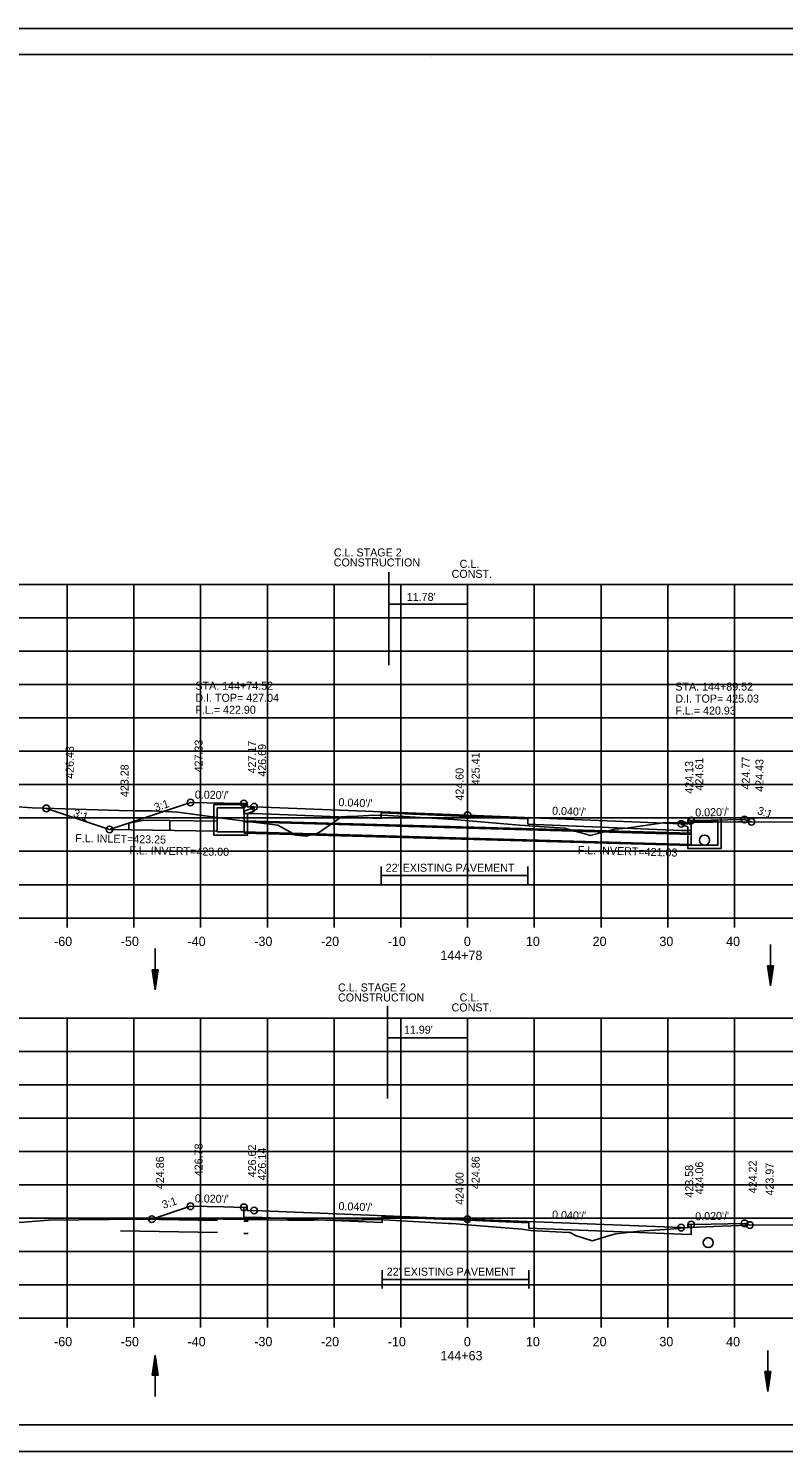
# Model space of a CAD drawing. Extents: x 1538688 to 1540766, y 656250 to 671912.
# Drawn here: x 1538792.4 to 1538905.5, y 663378.1 to 663591.4 of the extents above; entities that cross this region are included whole.
import ezdxf

# ---------------------------------------------------------------- set-up
doc = ezdxf.new("R2010")
doc.units = 0
for name, color, linetype in [('15', 7, 'Continuous'), ('18', 7, 'Continuous'), ('20', 7, 'Continuous'), ('22', 7, 'Continuous'), ('26', 7, 'Continuous'), ('39', 7, 'Continuous'), ('40', 7, 'Continuous'), ('41', 7, 'Continuous'), ('42', 7, 'Continuous'), ('7', 7, 'Continuous'), ('Borings', 7, 'Continuous'), ('Default', 7, 'Continuous'), ('Horizontal Alignment', 7, 'Continuous'), ('RipRap', 7, 'Continuous'), ('Wall Heights', 7, 'Continuous')]:
    doc.layers.add(name, color=color, linetype=linetype)

msp = doc.modelspace()

# ---------------------------------------------------------------- linework, layer by layer
at = {"layer": '15'}
for p, q in [((1538810.92, 663450.29), (1538811.37, 663447.29)), ((1538810.92, 663450.29), (1538811.82, 663450.29)), ((1538811, 663450.29), (1538811.37, 663447.79)), ((1538811.07, 663450.29), (1538811.37, 663448.3)), ((1538811.15, 663450.29), (1538811.37, 663448.8)), ((1538811.23, 663450.29), (1538811.37, 663449.31)), ((1538811.3, 663450.29), (1538811.37, 663449.81)), ((1538811.82, 663450.29), (1538811.37, 663447.29)), ((1538811.52, 663450.29), (1538811.37, 663449.31)), ((1538811.67, 663450.29), (1538811.37, 663448.3)), ((1538811.75, 663450.29), (1538811.37, 663447.79)), ((1538811.59, 663450.29), (1538811.37, 663448.8)), ((1538811.44, 663450.29), (1538811.37, 663449.81)), ((1538903.12, 663450.86), (1538903.57, 663447.86)), ((1538903.12, 663450.86), (1538904.02, 663450.86)), ((1538903.2, 663450.86), (1538903.57, 663448.36)), ((1538903.27, 663450.86), (1538903.57, 663448.88)), ((1538903.35, 663450.86), (1538903.57, 663449.38)), ((1538903.43, 663450.86), (1538903.57, 663449.89)), ((1538903.5, 663450.86), (1538903.57, 663450.39)), ((1538904.02, 663450.86), (1538903.57, 663447.86)), ((1538903.72, 663450.86), (1538903.57, 663449.89)), ((1538903.87, 663450.86), (1538903.57, 663448.88)), ((1538903.95, 663450.86), (1538903.57, 663448.36)), ((1538903.79, 663450.86), (1538903.57, 663449.38)), ((1538903.64, 663450.86), (1538903.57, 663450.39)), ((1538810.92, 663389.48), (1538811.37, 663392.48)), ((1538811.82, 663389.48), (1538811.37, 663392.48)), ((1538811, 663389.48), (1538811.37, 663391.98)), ((1538811.07, 663389.48), (1538811.37, 663391.46)), ((1538811.15, 663389.48), (1538811.37, 663390.96)), ((1538811.23, 663389.48), (1538811.37, 663390.45)), ((1538811.75, 663389.48), (1538811.37, 663391.98)), ((1538811.67, 663389.48), (1538811.37, 663391.46)), ((1538811.59, 663389.48), (1538811.37, 663390.96)), ((1538811.52, 663389.48), (1538811.37, 663390.45)), ((1538810.92, 663389.48), (1538811.82, 663389.48)), ((1538811.3, 663389.48), (1538811.37, 663389.95)), ((1538811.44, 663389.48), (1538811.37, 663389.95)), ((1538902.72, 663390.03), (1538903.17, 663387.03)), ((1538902.72, 663390.03), (1538903.62, 663390.03)), ((1538902.8, 663390.03), (1538903.17, 663387.54)), ((1538902.87, 663390.03), (1538903.17, 663388.05)), ((1538902.95, 663390.03), (1538903.17, 663388.55)), ((1538903.02, 663390.03), (1538903.17, 663389.06)), ((1538903.1, 663390.03), (1538903.17, 663389.56)), ((1538903.62, 663390.03), (1538903.17, 663387.03)), ((1538903.32, 663390.03), (1538903.17, 663389.06)), ((1538903.47, 663390.03), (1538903.17, 663388.05)), ((1538903.55, 663390.03), (1538903.17, 663387.54)), ((1538903.39, 663390.03), (1538903.17, 663388.55)), ((1538903.24, 663390.03), (1538903.17, 663389.56))]:
    msp.add_line(p, q, dxfattribs=at)
at = {"layer": '18'}
for points in [[(1538790.08, 663474.76), (1538792.95, 663474.53), (1538805.98, 663474.15), (1538808.36, 663474.1), (1538809.55, 663474.1), (1538810.94, 663474.11), (1538814.75, 663473.89), (1538823.98, 663472.66), (1538829.73, 663471.93), (1538831.53, 663470.96), (1538832.42, 663470.46), (1538834.02, 663470.3), (1538835.2, 663470.67), (1538835.61, 663470.68), (1538835.97, 663470.88), (1538839.3, 663473.22), (1538840.06, 663473.24), (1538840.87, 663473.27), (1538843.36, 663473.39), (1538844.95, 663473.45), (1538846.21, 663473.38), (1538856.06, 663472.81), (1538856.08, 663472.81), (1538865.94, 663471.97), (1538866.72, 663471.91), (1538866.84, 663471.9), (1538867.41, 663471.86), (1538872.69, 663471.52), (1538875.75, 663470.64), (1538876.57, 663470.38), (1538877.16, 663470.57), (1538880.25, 663471.34), (1538881.98, 663471.51), (1538887.47, 663472.29), (1538898.67, 663472.45), (1538898.91, 663472.46), (1538899.33, 663472.46), (1538922.45, 663472.39)], [(1538790.99, 663412.39), (1538795.38, 663412.73), (1538804.48, 663412.85), (1538813.49, 663412.91), (1538817.58, 663412.95), (1538821.55, 663412.89), (1538831.35, 663412.76), (1538835.22, 663412.74), (1538842.32, 663412.78), (1538842.73, 663412.78), (1538844.79, 663412.85), (1538855.29, 663412.26), (1538855.73, 663412.24), (1538855.85, 663412.23), (1538858.22, 663412.03), (1538866.31, 663411.4), (1538867.64, 663411.21), (1538869.46, 663411.11), (1538873.33, 663410.91), (1538873.55, 663410.91), (1538874.33, 663410.43), (1538876.83, 663409.63), (1538880, 663410.61), (1538880.39, 663410.71), (1538883.94, 663411.07), (1538888.53, 663411.4), (1538891.29, 663411.64), (1538900.19, 663412), (1538918.65, 663412.09)]]:
    msp.add_lwpolyline(points, dxfattribs=at)
at = {"layer": '20'}
for points in [[(1538795.06, 663474.47), (1538804.53, 663471.31), (1538816.67, 663475.36), (1538821.67, 663475.26), (1538824.67, 663475.2), (1538825.17, 663475.2), (1538825.18, 663474.7), (1538826.18, 663474.72), (1538858.18, 663473.44), (1538890.18, 663472.16), (1538891.18, 663472.14), (1538891.19, 663472.64), (1538891.69, 663472.64), (1538894.69, 663472.7), (1538899.69, 663472.8), (1538900.72, 663472.46)], [(1538810.88, 663412.89), (1538816.67, 663414.82), (1538821.67, 663414.72), (1538824.67, 663414.66), (1538825.17, 663414.66), (1538825.18, 663414.16), (1538826.18, 663414.18), (1538858.18, 663412.9), (1538890.18, 663411.62), (1538891.18, 663411.6), (1538891.19, 663412.1), (1538891.69, 663412.1), (1538894.69, 663412.16), (1538899.69, 663412.26), (1538900.45, 663412.01)]]:
    msp.add_lwpolyline(points, dxfattribs=at)
at = {"layer": '22'}
for p, q in [((1538718.18, 663508.03), (1538998.18, 663508.03)), ((1538798.18, 663458.03), (1538798.18, 663508.03)), ((1538808.18, 663458.03), (1538808.18, 663508.03)), ((1538818.18, 663458.03), (1538818.18, 663508.03)), ((1538828.18, 663458.03), (1538828.18, 663508.03)), ((1538838.18, 663458.03), (1538838.18, 663508.03)), ((1538848.18, 663458.03), (1538848.18, 663508.03)), ((1538858.18, 663458.03), (1538858.18, 663508.03)), ((1538868.18, 663458.03), (1538868.18, 663508.03)), ((1538878.18, 663458.03), (1538878.18, 663508.03)), ((1538888.18, 663458.03), (1538888.18, 663508.03)), ((1538898.18, 663458.03), (1538898.18, 663508.03)), ((1538718.18, 663503.03), (1538998.18, 663503.03)), ((1538718.18, 663498.03), (1538998.18, 663498.03)), ((1538718.18, 663493.03), (1538998.18, 663493.03)), ((1538718.18, 663488.03), (1538998.18, 663488.03)), ((1538718.18, 663483.03), (1538998.18, 663483.03)), ((1538718.18, 663478.03), (1538998.18, 663478.03)), ((1538718.18, 663473.03), (1538998.18, 663473.03)), ((1538718.18, 663468.03), (1538998.18, 663468.03)), ((1538718.18, 663463.03), (1538998.18, 663463.03)), ((1538718.18, 663458.03), (1538998.18, 663458.03)), ((1538718.18, 663443.03), (1538998.18, 663443.03)), ((1538798.18, 663398.03), (1538798.18, 663443.03)), ((1538808.18, 663398.03), (1538808.18, 663443.03)), ((1538818.18, 663398.03), (1538818.18, 663443.03)), ((1538828.18, 663398.03), (1538828.18, 663443.03)), ((1538838.18, 663398.03), (1538838.18, 663443.03)), ((1538848.18, 663398.03), (1538848.18, 663443.03)), ((1538858.18, 663398.03), (1538858.18, 663443.03)), ((1538868.18, 663398.03), (1538868.18, 663443.03)), ((1538878.18, 663398.03), (1538878.18, 663443.03)), ((1538888.18, 663398.03), (1538888.18, 663443.03)), ((1538898.18, 663398.03), (1538898.18, 663443.03)), ((1538718.18, 663438.03), (1538998.18, 663438.03)), ((1538718.18, 663433.03), (1538998.18, 663433.03)), ((1538718.18, 663428.03), (1538998.18, 663428.03)), ((1538718.18, 663423.03), (1538998.18, 663423.03)), ((1538718.18, 663418.03), (1538998.18, 663418.03)), ((1538718.18, 663413.03), (1538998.18, 663413.03)), ((1538718.18, 663408.03), (1538998.18, 663408.03)), ((1538718.18, 663403.03), (1538998.18, 663403.03)), ((1538718.18, 663398.03), (1538998.18, 663398.03))]:
    msp.add_line(p, q, dxfattribs=at)
at = {"layer": '26'}
for p, q in [((1538687.78, 663591.39), (1539021.11, 663591.39)), ((1538824.64, 663472.6), (1538891.73, 663470.73)), ((1538824.64, 663470.76), (1538891.73, 663468.9)), ((1538806.19, 663412.95), (1538820.69, 663412.7)), ((1538824.64, 663412.6), (1538825.31, 663412.58)), ((1538806.19, 663411.12), (1538820.69, 663410.87)), ((1538824.64, 663410.76), (1538825.31, 663410.75)), ((1538687.78, 663378.06), (1539021.11, 663378.06))]:
    msp.add_line(p, q, dxfattribs=at)
msp.add_lwpolyline([(1538687.77, 663591.39), (1539021.11, 663591.39), (1539021.11, 663378.05), (1538687.77, 663378.05)], close=True, dxfattribs=at)
for centre in [(1538816.67, 663475.36), (1538824.67, 663475.2), (1538795.06, 663474.47), (1538826.18, 663474.72), (1538858.18, 663473.44), (1538804.53, 663471.31), (1538890.18, 663472.16), (1538891.69, 663472.64), (1538899.69, 663472.8), (1538900.71, 663472.46), (1538816.67, 663414.82), (1538824.67, 663414.66), (1538826.18, 663414.18), (1538810.88, 663412.89), (1538858.18, 663412.9), (1538890.18, 663411.62), (1538891.69, 663412.1), (1538899.69, 663412.26), (1538900.45, 663412.01)]:
    msp.add_circle(centre, 0.5, dxfattribs=at)
at = {"layer": '39'}
for p, q in [((1538820.18, 663475.07), (1538824.93, 663475.07)), ((1538820.18, 663473.57), (1538820.18, 663475.07)), ((1538820.68, 663473.57), (1538820.68, 663474.57)), ((1538820.68, 663474.57), (1538824.68, 663474.57)), ((1538825.01, 663474.91), (1538824.68, 663474.57)), ((1538826.18, 663474.59), (1538824.68, 663474.07)), ((1538824.68, 663473.57), (1538824.68, 663474.07)), ((1538825.01, 663474.91), (1538824.93, 663475.07)), ((1538826.18, 663474.06), (1538825.18, 663473.72)), ((1538825.18, 663473.57), (1538825.18, 663473.72)), ((1538813.54, 663472.66), (1538820.69, 663472.53)), ((1538824.64, 663472.43), (1538891.73, 663470.57)), ((1538890.18, 663472.59), (1538891.68, 663472.07)), ((1538890.18, 663472.06), (1538891.18, 663471.71)), ((1538891.18, 663471.57), (1538891.18, 663471.71)), ((1538891.34, 663472.9), (1538891.43, 663473.07)), ((1538891.34, 663472.9), (1538891.68, 663472.57)), ((1538896.18, 663473.07), (1538891.43, 663473.07)), ((1538895.68, 663472.57), (1538891.68, 663472.57)), ((1538891.68, 663471.57), (1538891.68, 663472.07)), ((1538895.68, 663471.57), (1538895.68, 663472.57)), ((1538896.18, 663471.57), (1538896.18, 663473.07)), ((1538804.53, 663471.31), (1538820.69, 663471.03)), ((1538824.64, 663470.93), (1538891.73, 663469.07)), ((1538811.37, 663453.48), (1538811.37, 663447.29)), ((1538903.57, 663454.05), (1538903.57, 663447.86)), ((1538811.37, 663386.29), (1538811.37, 663392.48)), ((1538903.17, 663393.22), (1538903.17, 663387.03))]:
    msp.add_line(p, q, dxfattribs=at)
for points in [[(1538825.18, 663473.57), (1538825.18, 663470.43), (1538822.68, 663470.43), (1538820.18, 663470.43), (1538820.18, 663473.57)], [(1538824.68, 663473.57), (1538824.68, 663470.93), (1538822.68, 663470.93), (1538820.68, 663470.93), (1538820.68, 663473.57)], [(1538826.18, 663474.06), (1538826.18, 663474.59)], [(1538807.44, 663471.26), (1538807.41, 663472.26), (1538809.71, 663472.72), (1538813.54, 663472.66), (1538813.58, 663471.16)], [(1538890.18, 663472.06), (1538890.18, 663472.59)], [(1538896.18, 663471.57), (1538896.18, 663468.47), (1538893.68, 663468.47), (1538891.18, 663468.47), (1538891.18, 663471.57)], [(1538895.68, 663471.57), (1538895.68, 663468.97), (1538893.68, 663468.97), (1538891.68, 663468.97), (1538891.68, 663471.57)]]:
    msp.add_lwpolyline(points, dxfattribs=at)
for centre in [(1538893.68, 663469.72), (1538894.24, 663409.37)]:
    msp.add_circle(centre, 0.75, dxfattribs=at)
at = {"layer": '7'}
for p, q in [((1538845.21, 663465.78), (1538845.21, 663463.04)), ((1538867.21, 663465.78), (1538867.21, 663463.04)), ((1538867.21, 663464.41), (1538845.21, 663464.41)), ((1538845.36, 663405.24), (1538845.36, 663402.49)), ((1538867.36, 663403.86), (1538845.36, 663403.86)), ((1538867.36, 663405.24), (1538867.36, 663402.49))]:
    msp.add_line(p, q, dxfattribs=at)
at = {"layer": 'Borings'}
for p, q in [((1538718.18, 663458.03), (1538998.18, 663458.03)), ((1538798.18, 663456.63), (1538798.18, 663458.03)), ((1538808.18, 663456.63), (1538808.18, 663458.03)), ((1538818.18, 663456.63), (1538818.18, 663458.03)), ((1538828.18, 663456.63), (1538828.18, 663458.03)), ((1538838.18, 663456.63), (1538838.18, 663458.03)), ((1538848.18, 663456.63), (1538848.18, 663458.03)), ((1538858.18, 663456.63), (1538858.18, 663458.03)), ((1538868.18, 663456.63), (1538868.18, 663458.03)), ((1538878.18, 663456.63), (1538878.18, 663458.03)), ((1538888.18, 663456.63), (1538888.18, 663458.03)), ((1538898.18, 663456.63), (1538898.18, 663458.03)), ((1538718.18, 663398.03), (1538998.18, 663398.03)), ((1538798.18, 663396.63), (1538798.18, 663398.03)), ((1538808.18, 663396.63), (1538808.18, 663398.03)), ((1538818.18, 663396.63), (1538818.18, 663398.03)), ((1538828.18, 663396.63), (1538828.18, 663398.03)), ((1538838.18, 663396.63), (1538838.18, 663398.03)), ((1538848.18, 663396.63), (1538848.18, 663398.03)), ((1538858.18, 663396.63), (1538858.18, 663398.03)), ((1538868.18, 663396.63), (1538868.18, 663398.03)), ((1538878.18, 663396.63), (1538878.18, 663398.03)), ((1538888.18, 663396.63), (1538888.18, 663398.03)), ((1538898.18, 663396.63), (1538898.18, 663398.03))]:
    msp.add_line(p, q, dxfattribs=at)
at = {"layer": 'Default'}
for p, q in [((1538846.4, 663509.87), (1538846.4, 663495.96)), ((1538858.18, 663507.58), (1538858.18, 663502.58)), ((1538858.18, 663505.08), (1538846.4, 663505.08)), ((1538846.19, 663444.87), (1538846.19, 663430.96)), ((1538858.18, 663442.58), (1538858.18, 663437.58)), ((1538858.18, 663440.08), (1538846.19, 663440.08))]:
    msp.add_line(p, q, dxfattribs=at)
at = {"layer": 'RipRap'}
for p, q in [((1538700.18, 663587.49), (1539016.36, 663587.49)), ((1538852.7, 663587.23), (1538852.7, 663587.23)), ((1538852.7, 663587.23), (1538852.7, 663587.23)), ((1539016.36, 663382.03), (1538700.18, 663382.03))]:
    msp.add_line(p, q, dxfattribs=at)
at = {"layer": 'Wall Heights'}
for points in [[(1538891.69, 663472.64), (1538891.69, 663471.14), (1538890.18, 663471.16), (1538867.22, 663472.08), (1538867.22, 663472.91), (1538858.18, 663473.27), (1538845.22, 663473.79), (1538845.22, 663472.96), (1538826.18, 663473.72), (1538824.67, 663473.7), (1538824.67, 663475.2)], [(1538891.69, 663412.1), (1538891.69, 663410.6), (1538890.18, 663410.62), (1538867.37, 663411.53), (1538867.37, 663412.36), (1538858.18, 663412.73), (1538845.37, 663413.24), (1538845.37, 663412.41), (1538826.18, 663413.18), (1538824.67, 663413.16), (1538824.67, 663414.66)]]:
    msp.add_lwpolyline(points, dxfattribs=at)

# ---------------------------------------------------------------- texts
at = {"layer": '40'}
for s, p in [('STA. 144+74.52', (1538817.39, 663492.25)), ('STA. 144+89.52', (1538889.31, 663492.13)), ('D.I. TOP= 427.04', (1538817.39, 663490.45)), ('D.I. TOP= 425.03', (1538889.31, 663490.33)), ('F.L.= 422.90', (1538817.39, 663488.65)), ('F.L.= 420.93', (1538889.31, 663488.53))]:
    msp.add_text(s, height=1.2, dxfattribs=at).set_placement(p)
for s, rotation, p in [('F.L. INLET=423.25', 359.0081, (1538799.38, 663469.42)), ('F.L. INVERT=423.00', 359.0081, (1538807.49, 663467.6)), ('F.L. INVERT=421.03', 358.4067, (1538874.67, 663467.65))]:
    msp.add_text(s, height=1.2, rotation=rotation, dxfattribs=at).set_placement(p)
at = {"layer": '41'}
for s, p in [('427.33', (1538818.47, 663479.86)), ('427.17', (1538826.47, 663479.7)), ('426.43', (1538799.17, 663478.9)), ('426.69', (1538827.98, 663479.22)), ('425.41', (1538859.98, 663477.94)), ('424.77', (1538900.47, 663477.3)), ('423.28', (1538807.38, 663476.16)), ('424.60', (1538857.58, 663475.63)), ('424.13', (1538891.98, 663476.66)), ('424.61', (1538893.49, 663477.14)), ('424.43', (1538902.51, 663476.96)), ('426.78', (1538818.47, 663419.32)), ('426.62', (1538826.47, 663419.16)), ('426.14', (1538827.98, 663418.68)), ('424.86', (1538812.68, 663417.39)), ('424.86', (1538859.98, 663417.4)), ('423.58', (1538891.98, 663416.12)), ('424.06', (1538893.49, 663416.6)), ('424.22', (1538901.49, 663416.76)), ('423.97', (1538904.03, 663416.43)), ('424.00', (1538857.58, 663415.03))]:
    msp.add_text(s, height=1.2, rotation=90, dxfattribs=at).set_placement(p)
at = {"layer": '42'}
for s, rotation, p in [('3:1', 18.4349, (1538811.44, 663473.99)), ("0.020'/'", 358.8542, (1538817.3, 663475.95)), ("0.040'/'", 357.7094, (1538838.82, 663474.81)), ('3:1', 341.5651, (1538798.99, 663473.28)), ("0.040'/'", 357.7094, (1538870.82, 663473.53)), ("0.020'/'", 1.1458, (1538892.3, 663473.25)), ('3:1', 341.5651, (1538901.49, 663473.65)), ('3:1', 18.4349, (1538812.62, 663414.43)), ("0.020'/'", 358.8542, (1538817.3, 663415.41)), ("0.040'/'", 357.7094, (1538838.82, 663414.27)), ("0.040'/'", 357.7094, (1538870.82, 663412.99)), ("0.020'/'", 1.1458, (1538892.3, 663412.71))]:
    msp.add_text(s, height=1.2, rotation=rotation, dxfattribs=at).set_placement(p)
at = {"layer": '7'}
for p in [(1538845.91, 663464.97), (1538846.06, 663404.42)]:
    msp.add_text("22' EXISTING PAVEMENT", height=1.2, dxfattribs=at).set_placement(p)
at = {"layer": 'Default'}
for s, p in [('CONSTRUCTION', (1538838.13, 663510.74)), ('C.L. STAGE 2', (1538838.14, 663512.24)), ('CONST.', (1538855.78, 663509.03)), ('C.L.', (1538856.98, 663510.53)), ("11.78'", (1538849.07, 663505.58)), ('C.L. STAGE 2', (1538838.77, 663447.02)), ('CONSTRUCTION', (1538838.76, 663445.52)), ('C.L.', (1538856.98, 663445.53)), ('CONST.', (1538855.78, 663444.03)), ("11.99'", (1538848.64, 663440.69))]:
    msp.add_text(s, height=1.2, dxfattribs=at).set_placement(p)
at = {"layer": 'Horizontal Alignment'}
for s, p in [('-60', (1538796.22, 663453.83)), ('-50', (1538806.22, 663453.83)), ('-40', (1538816.22, 663453.83)), ('-30', (1538826.22, 663453.83)), ('-20', (1538836.22, 663453.83)), ('-10', (1538846.22, 663453.83)), ('0', (1538857.62, 663453.83)), ('10', (1538866.92, 663453.83)), ('20', (1538876.92, 663453.83)), ('30', (1538886.92, 663453.83)), ('40', (1538896.92, 663453.83)), ('144+78', (1538854.1, 663451.73)), ('-60', (1538796.22, 663393.83)), ('-50', (1538806.22, 663393.83)), ('-40', (1538816.22, 663393.83)), ('-30', (1538826.22, 663393.83)), ('-20', (1538836.22, 663393.83)), ('-10', (1538846.22, 663393.83)), ('0', (1538857.62, 663393.83)), ('10', (1538866.92, 663393.83)), ('20', (1538876.92, 663393.83)), ('30', (1538886.92, 663393.83)), ('40', (1538896.92, 663393.83)), ('144+63', (1538854.11, 663391.73))]:
    msp.add_text(s, height=1.4, dxfattribs=at).set_placement(p)

doc.saveas('drawing.dxf')
